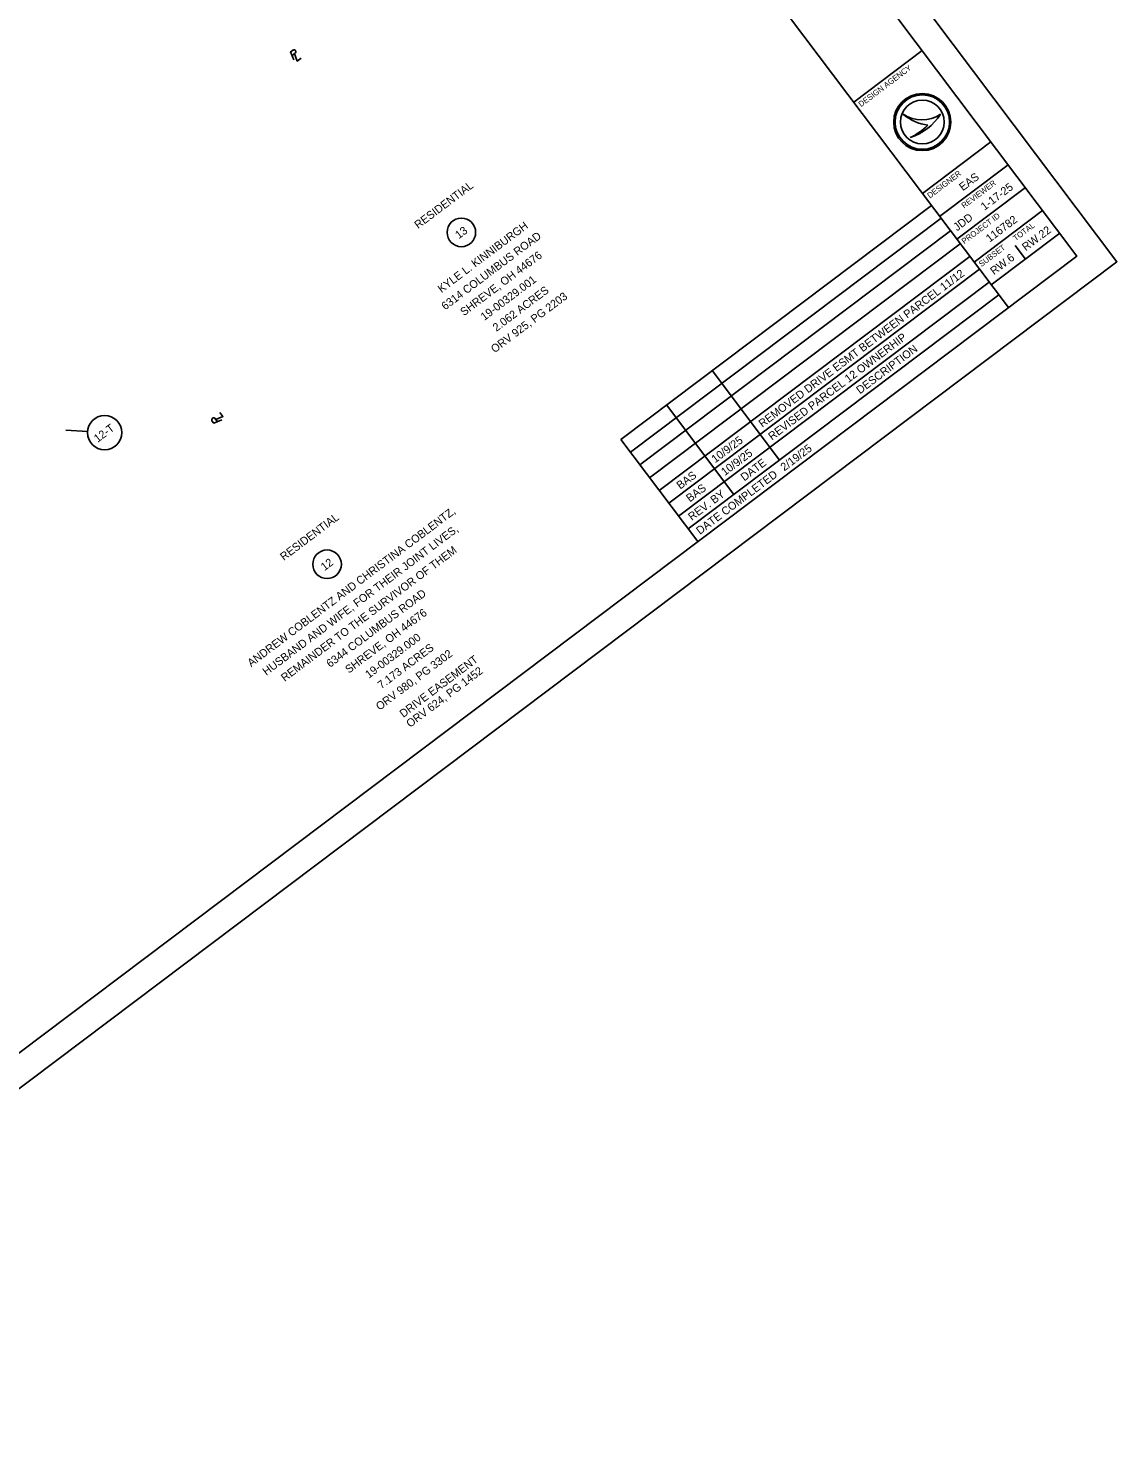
# Model space of a CAD drawing. Extents: x 120088 to 120896, y 463169 to 463930.
# Drawn here: x 120514.9 to 120895.8, y 463169.5 to 463660.3 of the extents above; entities that cross this region are included whole.
import ezdxf

# ---------------------------------------------------------------- set-up
doc = ezdxf.new("R2010")
doc.units = 0
for name, color, linetype in [('RD_X_Cells', 7, 'Continuous'), ('RD_X_RR_Cells', 7, 'Continuous'), ('SV_P_Mon_Cells_Set', 7, 'Continuous'), ('SV_X_Mon_Cells_Found', 7, 'Continuous'), ('SV_X_Shot_Marker', 7, 'Continuous')]:
    doc.layers.add(name, color=color, linetype=linetype)

msp = doc.modelspace()

# ---------------------------------------------------------------- linework, layer by layer
at = {"layer": 'RD_X_Cells'}
msp.add_lwpolyline([(120352.65, 463169.48), (120895.84, 463578.55), (120631.15, 463930.03), (120087.95, 463520.96)], close=True, dxfattribs=at)
at = {"layer": 'RD_X_RR_Cells'}
for p, q in [((120821.1, 463630.17), (120821.1, 463630.17)), ((120834.11, 463630.17), (120834.11, 463630.17)), ((120827.74, 463627.42), (120827.74, 463627.42)), ((120823.52, 463621.97), (120823.52, 463621.97)), ((120863.84, 463579.49), (120860.23, 463584.28))]:
    msp.add_line(p, q, dxfattribs=at)
for radius in [10, 9.54, 9.54, 7.64]:
    msp.add_circle((120827.74, 463627.42), radius, dxfattribs=at)
for centre, radius, start, end in [((120827.6, 463639.77), 11.6, 235.9088, 235.9151), ((120831.62, 463642.11), 15.91, 228.6211, 228.6253), ((120827.6, 463639.77), 11.6, 235.9151, 304.1489), ((120831.62, 463642.11), 15.91, 228.6253, 263.0778), ((120817.11, 463641.19), 20.26, 288.4408, 327.0664), ((120812.23, 463644.63), 25.32, 296.4827, 313.6504), ((120812.23, 463644.63), 25.32, 296.4795, 296.4827), ((120817.11, 463641.19), 20.26, 288.4359, 288.4408)]:
    msp.add_arc(centre, radius, start, end, dxfattribs=at)
at = {"layer": 'SV_P_Mon_Cells_Set'}
for p, q in [((120722.23, 463516.41), (120830.92, 463598.26)), ((120725.6, 463511.94), (120834.29, 463593.79)), ((120728.97, 463507.46), (120837.66, 463589.32)), ((120732.34, 463502.99), (120841.03, 463584.84)), ((120735.7, 463498.51), (120844.4, 463580.37)), ((120739.07, 463494.04), (120847.77, 463575.9)), ((120742.44, 463489.57), (120851.13, 463571.42)), ((120745.81, 463485.09), (120854.5, 463566.95)), ((120857.87, 463562.48), (120857.87, 463562.48)), ((120754.18, 463540.47), (120777.76, 463509.16)), ((120738.2, 463528.44), (120761.79, 463497.13)), ((120535.67, 463519.14), (120528.11, 463519.59)), ((120722.23, 463516.41), (120749.18, 463480.62))]:
    msp.add_line(p, q, dxfattribs=at)
for centre, radius in [((120666.47, 463588.81), 5), ((120541.66, 463518.77), 6), ((120619.48, 463472.7), 5)]:
    msp.add_circle(centre, radius, dxfattribs=at)
at = {"layer": 'SV_X_Mon_Cells_Found'}
for p, q in [((120857.87, 463562.48), (120605.21, 463897.98)), ((120803.73, 463634.37), (120827.69, 463652.42)), ((120827.79, 463602.42), (120851.76, 463620.47)), ((120833.81, 463594.43), (120857.77, 463612.48)), ((120839.83, 463586.44), (120863.79, 463604.49)), ((120845.84, 463578.45), (120869.81, 463596.5)), ((120851.86, 463570.47), (120875.82, 463588.51))]:
    msp.add_line(p, q, dxfattribs=at)
msp.add_lwpolyline([(120117.93, 463531.02), (120629.17, 463916.03), (120881.84, 463580.52), (120370.6, 463195.51)], close=True, dxfattribs=at)
at = {"layer": 'SV_X_Shot_Marker'}
for p, q in [((120607.28, 463650.68), (120608.31, 463651.46)), ((120608.29, 463650.67), (120608.29, 463650.67)), ((120581.15, 463522.62), (120580.37, 463523.66)), ((120581.16, 463523.63), (120581.16, 463523.63))]:
    msp.add_line(p, q, dxfattribs=at)
for points in [[(120607.9, 463649.16), (120606.74, 463652), (120607.57, 463652.62)], [(120607.93, 463651.59), (120609.08, 463648.75), (120610.47, 463649.81)], [(120582.67, 463523.24), (120579.83, 463522.08), (120579.21, 463522.91)], [(120580.24, 463523.27), (120583.07, 463524.42), (120582.02, 463525.81)]]:
    msp.add_lwpolyline(points, dxfattribs=at)
for centre, start, end in [((120607.89, 463652.01), 307.4541, 118.3112), ((120579.82, 463523.24), 37.4541, 208.3112)]:
    msp.add_arc(centre, 0.69, start, end, dxfattribs=at)

# ---------------------------------------------------------------- texts
at = {"layer": 'RD_X_RR_Cells'}
for s, height, p in [('DESIGN AGENCY', 2, (120806.33, 463632.58)), ('DESIGNER', 2, (120830.4, 463600.62)), ('EAS', 2.8, (120841.92, 463603.17)), ('REVIEWER', 2, (120842.35, 463597.11)), ('1-17-25', 2.8, (120849.5, 463596.36)), ('JDD', 2.8, (120839.91, 463589.13)), ('PROJECT ID', 2, (120842.43, 463584.65)), ('116782', 2.8, (120851.3, 463585.2)), ('TOTAL', 2, (120860.43, 463585.68)), ('RW.22', 2.8, (120863.93, 463582.18)), ('SUBSET', 2, (120848.44, 463576.66)), ('RW.6', 2.8, (120852.81, 463573.81))]:
    msp.add_text(s, height=height, rotation=36.9831, dxfattribs=at).set_placement(p)
at = {"layer": 'SV_P_Mon_Cells_Set'}
for s, p in [('RESIDENTIAL', (120651.35, 463589.94)), ('KYLE L. KINNIBURGH', (120659.51, 463567.54)), ('13', (120665.6, 463586.4)), ('6314 COLUMBUS ROAD', (120660.79, 463561.49)), ('SHREVE, OH 44676', (120667.39, 463559.45)), ('REMOVED DRIVE ESMT BETWEEN PARCEL 11/12  ', (120771.78, 463520.43)), ('19-00329.001', (120674.53, 463557.82)), ('ORV 925, PG 2203', (120678.11, 463546.5)), ('2.062 ACRES', (120678.75, 463553.99)), ('REVISED PARCEL 12 OWNERHIP             ', (120775.15, 463515.95)), ('DESCRIPTION', (120805.93, 463532.12)), ('12-T', (120539.2, 463515.17)), (' 10/9/25', (120754.45, 463507.38)), (' 10/9/25', (120757.82, 463502.9)), ('2/19/25                             ', (120779.45, 463505.17)), ('DATE', (120765.47, 463501.65)), ('BAS', (120743.05, 463498.79)), ('DATE COMPLETED', (120749.93, 463482.94)), ('BAS', (120746.42, 463494.32)), ('REV. BY', (120747.11, 463487.82)), ('ANDREW COBLENTZ AND CHRISTINA COBLENTZ,', (120592.92, 463436.67)), ('RESIDENTIAL', (120604.36, 463473.83)), ('HUSBAND AND WIFE, FOR THEIR JOINT LIVES,', (120598.23, 463433.66)), ('REMAINDER TO THE SURVIVOR OF THEM', (120604.68, 463431.51)), ('12', (120618.6, 463470.28)), ('6344 COLUMBUS ROAD', (120620.54, 463436.43)), ('SHREVE, OH 44676', (120627.13, 463434.39)), ('19-00329.000', (120634.12, 463432.65)), ('ORV 980, PG 3302', (120637.85, 463421.43)), ('7.173 ACRES', (120638.49, 463428.93)), ('DRIVE EASEMENT', (120646.16, 463418.92)), ('ORV 624, PG 1452', (120648.52, 463415.44))]:
    msp.add_text(s, height=2.8, rotation=36.9831, dxfattribs=at).set_placement(p)

doc.saveas('drawing.dxf')
